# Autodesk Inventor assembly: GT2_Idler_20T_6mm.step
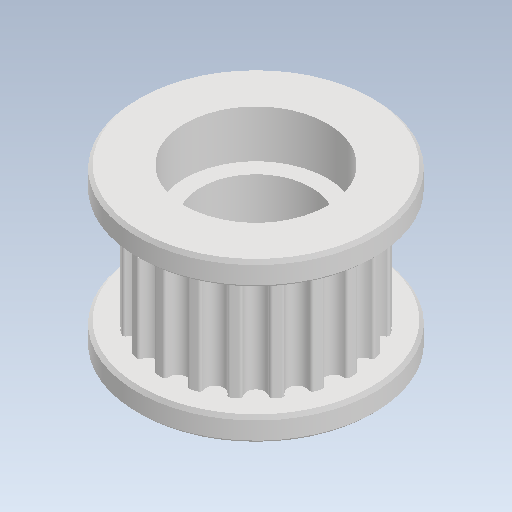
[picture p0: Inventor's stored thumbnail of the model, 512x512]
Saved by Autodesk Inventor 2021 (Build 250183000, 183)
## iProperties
Created: 2023-10
Part Number: GT2_Idler_20T_6mm.step
Document SubType Name: Assembly
Designer: hp
Author: hp
Revision Number: ANY
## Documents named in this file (2)
- C:\Users\hp\Downloads\low-cost-linear-guide-for-automation-training-with-nema-17-1.snapshot.1\GT2_Idler_20T_6mm.step.iam
- C:\Users\hp\Downloads\low-cost-linear-guide-for-automation-training-with-nema-17-1.snapshot.1\GT2_Idler_20T.step.ipt
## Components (1 placed, 1 different names)
1. GT2_Idler_20T.step_12
